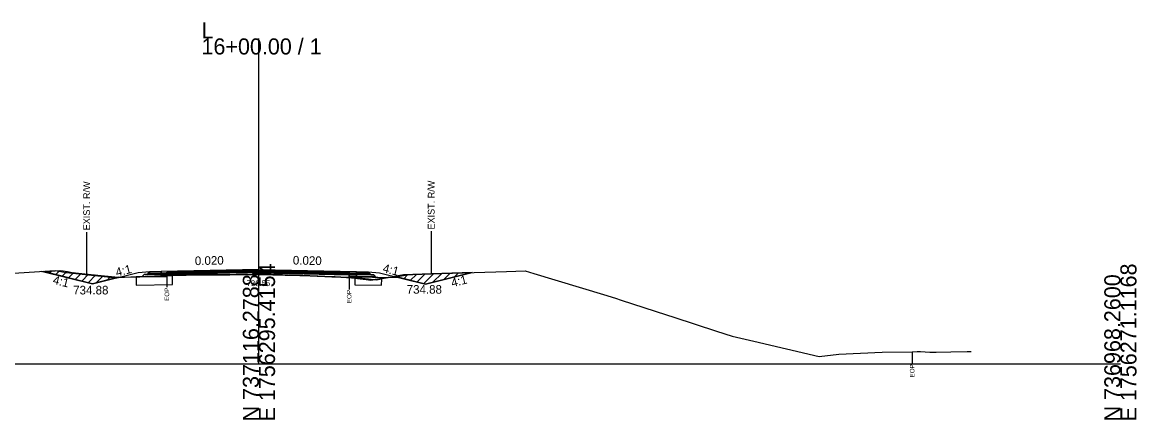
# Model space of a CAD drawing. Extents: x -26 to 4303, y -10 to 9577.
# Drawn here: x 108.8 to 302.8, y 5990.3 to 6059.4 of the extents above; entities that cross this region are included whole.
import ezdxf

# ---------------------------------------------------------------- set-up
doc = ezdxf.new("R2010")
doc.units = 0
for name, color, linetype in [('Exist CMT Pavement', 7, 'Continuous'), ('Old_Level_2', 7, 'Continuous'), ('Pattern 1', 7, 'Continuous'), ('Prop CMT Conc Surface', 7, 'Continuous'), ('Prop CMT Concrete Structures', 7, 'Continuous'), ('Prop CMT Pvmt Course 1', 7, 'Continuous'), ('Prop CMT Pvmt Course 1 CG', 7, 'Continuous'), ('Prop CMT Pvmt Course 1 Wedge', 7, 'Continuous'), ('Prop CMT Pvmt Course 2', 7, 'Continuous'), ('Prop CMT Pvmt Course 2 Wedge', 7, 'Continuous'), ('Prop CMT Pvmt Course 3', 7, 'Continuous'), ('Prop CMT Pvmt Surface', 7, 'Continuous'), ('Prop CMT Pvmt Surface Shoulder', 7, 'Continuous'), ('Prop CMT Pvmt Wedge Surface 1', 7, 'Continuous'), ('Prop CMT Pvmt Wedge Surface 2', 7, 'Continuous'), ('Prop CMT Pvmt Wedge Surface 3', 7, 'Continuous'), ('Prop CMT Shld Paved Course 1', 7, 'Continuous'), ('Prop CMT Shld Paved Course 2', 7, 'Continuous'), ('Prop CMT Shld Paved Course 3', 7, 'Continuous'), ('Prop CMT Slope Grass', 7, 'Continuous'), ('Prop CMT Subgrade Earthwork', 7, 'Continuous'), ('Prop Road Sect_ Recs - UC Shallow (Outline)', 7, 'Continuous'), ('Prop Shade Light', 7, 'Continuous'), ('Prop XS DDE Elevations', 7, 'Continuous'), ('Prop XS Ditch Standard Text', 7, 'Continuous'), ('Prop XS Hydro Elevations', 7, 'Continuous'), ('Prop XS SE Text', 7, 'Continuous'), ('Prop XS Side Slope Text', 7, 'Continuous'), ('Prop XS Wedging', 7, 'Continuous')]:
    doc.layers.add(name, color=color, linetype=linetype)

msp = doc.modelspace()

# ---------------------------------------------------------------- linework, layer by layer
at = {"layer": 'Exist CMT Pavement'}
for points in [[(150, 6016.42), (133, 6016.08)], [(150, 6016.42), (167, 6016.08)]]:
    msp.add_lwpolyline(points, dxfattribs=at)
at = {"layer": 'Old_Level_2'}
for p, q in [((150, 6000), (150, 6056.65)), ((150, 6000), (150, 6056.65)), ((0, 6000), (150, 6000)), ((0, 6000), (150, 6000)), ((150, 6000), (300, 6000)), ((150, 6000), (300, 6000))]:
    msp.add_line(p, q, dxfattribs=at)
at = {"layer": 'Pattern 1'}
for p, q in [((113.48, 6015.84), (113.81, 6016.16)), ((114.61, 6015.55), (115.32, 6016.26)), ((115.74, 6015.27), (116.56, 6016.09)), ((116.87, 6014.99), (117.79, 6015.9)), ((118.01, 6014.7), (119.06, 6015.76)), ((119.14, 6014.42), (120.34, 6015.63)), ((120.27, 6014.14), (121.62, 6015.49)), ((121.67, 6014.12), (122.9, 6015.35)), ((175.29, 6014.88), (175.84, 6015.43)), ((176.42, 6014.6), (177.36, 6015.53)), ((177.56, 6014.32), (178.83, 6015.59)), ((178.69, 6014.03), (180.31, 6015.65)), ((180.36, 6014.3), (181.77, 6015.7)), ((182.25, 6014.77), (183.23, 6015.75)), ((184.13, 6015.24), (184.7, 6015.8)), ((186.02, 6015.71), (186.16, 6015.85)), ((123.55, 6014.59), (124.17, 6015.22)), ((125.44, 6015.06), (125.45, 6015.08)), ((125.84, 6015.09), (125.85, 6015.1)), ((125.85, 6015.1), (125.85, 6015.1))]:
    msp.add_line(p, q, dxfattribs=at)
for points in [[(125.48, 6015.08), (121, 6013.96), (112.51, 6016.08), (115.5, 6016.27), (116.65, 6016.07), (117.47, 6015.93), (121.38, 6015.51)], [(179, 6013.96), (186.64, 6015.86), (185.58, 6015.83), (180.42, 6015.66), (176.36, 6015.49), (175.82, 6015.43), (174.17, 6015.16)]]:
    msp.add_lwpolyline(points, close=True, dxfattribs=at)
msp.add_lwpolyline([(134.96, 6015.42), (134.96, 6015.32), (130.32, 6015.22), (132.36, 6015.31), (133.86, 6015.38), (134.96, 6015.42)], dxfattribs=at)
at = {"layer": 'Prop CMT Conc Surface'}
for points in [[(133.97, 6015.85), (133, 6015.83)], [(133, 6015.83), (133, 6015.62)], [(133, 6015.62), (133.97, 6015.64)], [(133.97, 6015.64), (133.97, 6015.85)], [(165.71, 6015.65), (165.71, 6015.86)], [(165.71, 6015.86), (167, 6015.83)], [(167, 6015.62), (165.71, 6015.65)], [(167, 6015.83), (167, 6015.62)]]:
    msp.add_lwpolyline(points, dxfattribs=at)
at = {"layer": 'Prop CMT Concrete Structures'}
for points in [[(133, 6015.83), (133, 6016.08)], [(133.97, 6015.85), (133, 6015.83)], [(150, 6016.3), (133.97, 6015.98)], [(133.97, 6015.98), (133.97, 6015.85)], [(150, 6016.3), (165.71, 6015.98)], [(165.71, 6015.98), (165.71, 6015.86)], [(165.71, 6015.86), (167, 6015.83)], [(167, 6015.83), (167, 6016.08)]]:
    msp.add_lwpolyline(points, dxfattribs=at)
at = {"layer": 'Prop CMT Pvmt Course 1'}
for points in [[(133.97, 6015.64), (133, 6015.62)], [(133, 6015.62), (133, 6015.29)], [(133.97, 6015.31), (133.97, 6015.64)], [(165.71, 6015.65), (167, 6015.62)], [(165.71, 6015.19), (165.71, 6015.65)], [(167, 6015.62), (167, 6015.29)], [(133, 6015.29), (133.97, 6015.31)], [(167, 6015.29), (165.71, 6015.32)]]:
    msp.add_lwpolyline(points, dxfattribs=at)
at = {"layer": 'Prop CMT Pvmt Course 1 Wedge'}
for points in [[(133.97, 6015.64), (134.04, 6015.65), (134.07, 6015.65), (134.14, 6015.65), (134.98, 6015.66), (135.35, 6015.67), (137.23, 6015.71), (137.36, 6015.71), (138.42, 6015.73), (139.9, 6015.76), (140.59, 6015.78), (142.43, 6015.81), (142.77, 6015.82), (144.85, 6015.86), (144.96, 6015.86), (146.02, 6015.89), (146.32, 6015.89), (146.51, 6015.89), (146.58, 6015.9), (147.02, 6015.9), (147.14, 6015.91), (147.5, 6015.91), (148.02, 6015.92), (150, 6015.96)], [(133.97, 6015.42), (133.97, 6015.64)], [(150, 6015.55), (148.02, 6015.58), (147.5, 6015.58), (147.14, 6015.57), (147.02, 6015.58), (146.58, 6015.57), (146.51, 6015.57), (146.32, 6015.57), (146.02, 6015.56), (144.96, 6015.54), (144.85, 6015.54), (142.77, 6015.54), (142.43, 6015.54), (140.59, 6015.52), (139.9, 6015.51), (138.42, 6015.49), (137.36, 6015.47), (137.23, 6015.47), (135.35, 6015.47), (134.98, 6015.45), (134.14, 6015.43), (134.07, 6015.43), (134.04, 6015.43), (133.97, 6015.42)], [(150, 6015.96), (150, 6015.55)], [(150, 6015.96), (150.03, 6015.96), (151.47, 6015.94), (151.98, 6015.92), (152.41, 6015.92), (152.91, 6015.91), (153.24, 6015.9), (154.08, 6015.88), (154.56, 6015.87), (155.1, 6015.86), (157.11, 6015.82), (157.63, 6015.81), (160.14, 6015.76), (160.16, 6015.76), (160.28, 6015.76), (162.7, 6015.71), (163.25, 6015.7), (165.27, 6015.66), (165.28, 6015.66), (165.28, 6015.66), (165.28, 6015.66), (165.45, 6015.66), (165.49, 6015.65), (165.5, 6015.65), (165.59, 6015.65), (165.71, 6015.65)], [(165.71, 6015.03), (165.59, 6015.05), (165.5, 6015.05), (165.49, 6015.05), (165.45, 6015.06), (165.28, 6015.06), (165.28, 6015.06), (165.28, 6015.06), (165.27, 6015.06), (163.25, 6015.16), (162.7, 6015.18), (160.28, 6015.27), (160.16, 6015.27), (160.14, 6015.27), (157.63, 6015.38), (157.11, 6015.4), (155.1, 6015.46), (154.56, 6015.47), (154.08, 6015.49), (153.24, 6015.51), (152.91, 6015.52), (152.41, 6015.54), (151.98, 6015.55), (151.47, 6015.55), (150.03, 6015.55), (150, 6015.55)], [(165.71, 6015.65), (165.71, 6015.03)]]:
    msp.add_lwpolyline(points, dxfattribs=at)
at = {"layer": 'Prop CMT Pvmt Course 2'}
for points in [[(133, 6016.08), (131, 6016.04), (130.74, 6015.79)], [(130.74, 6015.79), (133, 6015.83)], [(133, 6015.83), (133, 6016.08)], [(167, 6016.08), (169, 6016.04), (169.26, 6015.79)], [(167, 6015.83), (167, 6016.08)], [(169.26, 6015.79), (167, 6015.83)]]:
    msp.add_lwpolyline(points, dxfattribs=at)
at = {"layer": 'Prop CMT Pvmt Course 2 Wedge'}
for points in [[(131, 6016.04), (129, 6015.88), (121, 6013.88), (112.08, 6016.11)], [(169, 6016.04), (171, 6015.88), (179, 6013.88), (187.13, 6015.91)]]:
    msp.add_lwpolyline(points, dxfattribs=at)
at = {"layer": 'Prop CMT Pvmt Course 3'}
for points in [[(133, 6015.83), (130.74, 6015.79), (130.53, 6015.58)], [(130.53, 6015.58), (133, 6015.62)], [(133, 6015.62), (133, 6015.83)], [(167, 6015.83), (169.26, 6015.79), (169.47, 6015.58)], [(167, 6015.62), (167, 6015.83)], [(169.47, 6015.58), (167, 6015.62)]]:
    msp.add_lwpolyline(points, dxfattribs=at)
at = {"layer": 'Prop CMT Pvmt Surface'}
for points in [[(150, 6016.17), (133, 6015.83)], [(133, 6015.83), (133, 6016.08)], [(150, 6016.17), (167, 6015.83)], [(167, 6015.83), (167, 6016.08)]]:
    msp.add_lwpolyline(points, dxfattribs=at)
at = {"layer": 'Prop CMT Pvmt Surface Shoulder'}
for points in [[(133.97, 6015.42), (134.04, 6015.43), (134.07, 6015.43), (134.14, 6015.43), (134.98, 6015.45), (135.35, 6015.47), (137.23, 6015.47), (137.36, 6015.47), (138.42, 6015.49), (139.9, 6015.51), (140.59, 6015.52), (142.43, 6015.54), (142.77, 6015.54), (144.85, 6015.54), (144.96, 6015.54), (146.02, 6015.56), (146.32, 6015.57), (146.51, 6015.57), (146.58, 6015.57), (147.02, 6015.58), (147.14, 6015.57), (147.5, 6015.58), (148.02, 6015.58), (150, 6015.55)], [(150, 6015.55), (150.03, 6015.55), (151.47, 6015.55), (151.98, 6015.55), (152.41, 6015.54), (152.91, 6015.52), (153.24, 6015.51), (154.08, 6015.49), (154.56, 6015.47), (155.1, 6015.46), (157.11, 6015.4), (157.63, 6015.38), (160.14, 6015.27), (160.16, 6015.27), (160.28, 6015.27), (162.7, 6015.18), (163.25, 6015.16), (165.27, 6015.06), (165.28, 6015.06), (165.28, 6015.06), (165.28, 6015.06), (165.45, 6015.06), (165.49, 6015.05), (165.5, 6015.05), (165.59, 6015.05), (165.7, 6015.03)]]:
    msp.add_lwpolyline(points, dxfattribs=at)
at = {"layer": 'Prop CMT Pvmt Wedge Surface 1'}
for p, q in [((133.02, 6015.17), (125.53, 6015.02)), ((133.97, 6015.19), (133.02, 6015.17)), ((165.7, 6015.19), (166.98, 6015.17)), ((166.98, 6015.17), (174.47, 6015.02))]:
    msp.add_line(p, q, dxfattribs=at)
for points in [[(133.97, 6015.19), (133.97, 6015.42)], [(165.7, 6015.19), (165.7, 6015.03)]]:
    msp.add_lwpolyline(points, dxfattribs=at)
at = {"layer": 'Prop CMT Pvmt Wedge Surface 2'}
for points in [[(133.97, 6015.98), (134.04, 6015.98), (134.07, 6015.98), (134.14, 6015.98), (134.98, 6016), (135.35, 6016), (137.23, 6016.04), (137.36, 6016.05), (138.42, 6016.07), (139.9, 6016.1), (140.59, 6016.11), (142.43, 6016.15), (142.77, 6016.15), (144.85, 6016.19), (144.96, 6016.2), (146.02, 6016.22), (146.32, 6016.22), (146.51, 6016.23), (146.58, 6016.23), (147.02, 6016.24), (147.14, 6016.24), (147.5, 6016.25), (148.02, 6016.26), (150, 6016.3)], [(150, 6016.17), (148.02, 6016.13), (147.5, 6016.12), (147.14, 6016.12), (147.02, 6016.11), (146.58, 6016.1), (146.51, 6016.1), (146.32, 6016.1), (146.02, 6016.09), (144.96, 6016.07), (144.85, 6016.07), (142.77, 6016.03), (142.43, 6016.02), (140.59, 6015.98), (139.9, 6015.97), (138.42, 6015.94), (137.36, 6015.92), (137.23, 6015.92), (135.35, 6015.88), (134.98, 6015.87), (134.14, 6015.86), (134.07, 6015.85), (134.04, 6015.85), (133.97, 6015.85)], [(133.97, 6015.85), (133.97, 6015.98)], [(150, 6016.3), (150, 6016.17)], [(150, 6016.3), (150.03, 6016.3), (151.47, 6016.27), (151.98, 6016.26), (152.41, 6016.25), (152.91, 6016.24), (153.24, 6016.23), (154.08, 6016.22), (154.56, 6016.21), (155.1, 6016.2), (157.11, 6016.16), (157.63, 6016.15), (160.14, 6016.1), (160.16, 6016.09), (160.28, 6016.09), (162.7, 6016.04), (163.25, 6016.03), (165.27, 6015.99), (165.28, 6015.99), (165.28, 6015.99), (165.28, 6015.99), (165.45, 6015.99), (165.49, 6015.99), (165.5, 6015.99), (165.59, 6015.99), (165.71, 6015.98)], [(165.71, 6015.86), (165.59, 6015.86), (165.5, 6015.86), (165.49, 6015.86), (165.45, 6015.86), (165.28, 6015.87), (165.28, 6015.87), (165.28, 6015.87), (165.27, 6015.87), (163.25, 6015.91), (162.7, 6015.92), (160.28, 6015.97), (160.16, 6015.97), (160.14, 6015.97), (157.63, 6016.02), (157.11, 6016.03), (155.1, 6016.07), (154.56, 6016.08), (154.08, 6016.09), (153.24, 6016.11), (152.91, 6016.11), (152.41, 6016.12), (151.98, 6016.13), (151.47, 6016.14), (150.03, 6016.17), (150, 6016.17)], [(165.71, 6015.98), (165.71, 6015.86)]]:
    msp.add_lwpolyline(points, dxfattribs=at)
at = {"layer": 'Prop CMT Pvmt Wedge Surface 3'}
for points in [[(133.97, 6015.85), (134.04, 6015.85), (134.07, 6015.85), (134.14, 6015.86), (134.98, 6015.87), (135.35, 6015.88), (137.23, 6015.92), (137.36, 6015.92), (138.42, 6015.94), (139.9, 6015.97), (140.59, 6015.98), (142.43, 6016.02), (142.77, 6016.03), (144.85, 6016.07), (144.96, 6016.07), (146.02, 6016.09), (146.32, 6016.1), (146.51, 6016.1), (146.58, 6016.1), (147.02, 6016.11), (147.14, 6016.12), (147.5, 6016.12), (148.02, 6016.13), (150, 6016.17)], [(150, 6015.96), (148.02, 6015.92), (147.5, 6015.91), (147.14, 6015.91), (147.02, 6015.9), (146.58, 6015.9), (146.51, 6015.89), (146.32, 6015.89), (146.02, 6015.89), (144.96, 6015.86), (144.85, 6015.86), (142.77, 6015.82), (142.43, 6015.81), (140.59, 6015.78), (139.9, 6015.76), (138.42, 6015.73), (137.36, 6015.71), (137.23, 6015.71), (135.35, 6015.67), (134.98, 6015.66), (134.14, 6015.65), (134.07, 6015.65), (134.04, 6015.65), (133.97, 6015.64)], [(133.97, 6015.64), (133.97, 6015.85)], [(150, 6016.17), (150, 6015.96)], [(150, 6016.17), (150.03, 6016.17), (151.47, 6016.14), (151.98, 6016.13), (152.41, 6016.12), (152.91, 6016.11), (153.24, 6016.11), (154.08, 6016.09), (154.56, 6016.08), (155.1, 6016.07), (157.11, 6016.03), (157.63, 6016.02), (160.14, 6015.97), (160.16, 6015.97), (160.28, 6015.97), (162.7, 6015.92), (163.25, 6015.91), (165.27, 6015.87), (165.28, 6015.87), (165.28, 6015.87), (165.28, 6015.87), (165.45, 6015.86), (165.49, 6015.86), (165.5, 6015.86), (165.59, 6015.86), (165.71, 6015.86)], [(165.71, 6015.65), (165.59, 6015.65), (165.5, 6015.65), (165.49, 6015.65), (165.45, 6015.66), (165.28, 6015.66), (165.28, 6015.66), (165.28, 6015.66), (165.27, 6015.66), (163.25, 6015.7), (162.7, 6015.71), (160.28, 6015.76), (160.16, 6015.76), (160.14, 6015.76), (157.63, 6015.81), (157.11, 6015.82), (155.1, 6015.86), (154.56, 6015.87), (154.08, 6015.88), (153.24, 6015.9), (152.91, 6015.91), (152.41, 6015.92), (151.98, 6015.92), (151.47, 6015.94), (150.03, 6015.96), (150, 6015.96)], [(165.71, 6015.86), (165.71, 6015.65)]]:
    msp.add_lwpolyline(points, dxfattribs=at)
at = {"layer": 'Prop CMT Shld Paved Course 1'}
for points in [[(133, 6015.62), (133, 6016.08)], [(150, 6015.96), (133, 6015.62)], [(150, 6015.96), (167, 6015.62)], [(167, 6015.62), (167, 6016.08)]]:
    msp.add_lwpolyline(points, dxfattribs=at)
at = {"layer": 'Prop CMT Shld Paved Course 2'}
for points in [[(133, 6016.08), (131, 6016.04)], [(167, 6016.08), (169, 6016.04)]]:
    msp.add_lwpolyline(points, dxfattribs=at)
at = {"layer": 'Prop CMT Shld Paved Course 3'}
for points in [[(150, 6016.42), (133, 6016.08)], [(133, 6016.08), (133, 6015.83)], [(133, 6015.83), (133.97, 6015.85)], [(133.97, 6015.98), (150, 6016.3)], [(133.97, 6015.85), (133.97, 6015.98)], [(150, 6016.42), (167, 6016.08)], [(165.71, 6015.98), (150, 6016.3)], [(165.71, 6015.86), (165.71, 6015.98)], [(167, 6015.83), (165.71, 6015.86)], [(167, 6016.08), (167, 6015.83)]]:
    msp.add_lwpolyline(points, dxfattribs=at)
at = {"layer": 'Prop CMT Slope Grass'}
msp.add_lwpolyline([(106.37, 6015.74), (114.51, 6016.27), (116.45, 6015.94), (124.76, 6015.05), (125.14, 6015.07), (129.54, 6015.23), (134.04, 6015.43), (134.98, 6015.45), (135.35, 6015.47), (137.36, 6015.47), (138.42, 6015.49), (139.9, 6015.51), (140.59, 6015.52), (142.43, 6015.54), (144.96, 6015.54), (146.02, 6015.56), (146.51, 6015.57), (147.14, 6015.57), (147.5, 6015.58), (148.02, 6015.58), (150.03, 6015.55), (151.47, 6015.55), (152.56, 6015.53), (152.91, 6015.52), (154.06, 6015.49), (154.56, 6015.47), (155.1, 6015.46), (157.11, 6015.4), (157.63, 6015.38), (160.28, 6015.27), (162.7, 6015.18), (163.25, 6015.16), (165.49, 6015.05), (165.59, 6015.05), (168.69, 6014.68), (169.44, 6014.58), (171.82, 6014.95), (175.19, 6015.49), (180.05, 6015.68), (181.84, 6015.74), (193.13, 6016.11), (196.35, 6016.23), (197.88, 6015.76), (210.01, 6012.07), (212.11, 6011.43), (213.09, 6011.11), (220.95, 6008.56), (222.24, 6008.14), (229.66, 6005.69), (232.38, 6004.85), (236.15, 6003.99), (247.52, 6001.31), (250.99, 6001.73), (258.5, 6002.07), (263.74, 6002.11), (264.63, 6002.18), (265.2, 6002.18), (266.79, 6002.06), (267.93, 6002.04), (270.5, 6002.11), (273.32, 6002.17), (273.99, 6002.18)], dxfattribs=at)
at = {"layer": 'Prop CMT Subgrade Earthwork'}
for points in [[(133, 6015.62), (130.53, 6015.58), (130.03, 6015.57), (129.69, 6015.23)], [(133, 6015.29), (133, 6015.62)], [(167, 6015.62), (169.47, 6015.58), (169.97, 6015.57), (170.31, 6015.23)], [(167, 6015.29), (167, 6015.62)], [(129.69, 6015.23), (133, 6015.29)], [(170.31, 6015.23), (167, 6015.29)]]:
    msp.add_lwpolyline(points, dxfattribs=at)
at = {"layer": 'Prop Road Sect_ Recs - UC Shallow (Outline)'}
for points in [[(128.64, 6013.69), (134.96, 6013.82), (134.96, 6015.32), (130.2, 6015.22), (128.61, 6015.16)], [(166.7, 6013.79), (171.36, 6013.69), (171.38, 6014.73), (170.44, 6014.58), (169.06, 6014.76), (167.4, 6014.95), (166.7, 6015.03)]]:
    msp.add_lwpolyline(points, close=True, dxfattribs=at)
at = {"layer": 'Prop Shade Light'}
for points in [[(128.64, 6013.69), (134.96, 6013.82), (134.96, 6015.32), (130.2, 6015.22), (128.61, 6015.16), (128.64, 6013.69)], [(166.7, 6013.79), (171.36, 6013.69), (171.38, 6014.73), (170.44, 6014.58), (169.06, 6014.76), (167.4, 6014.95), (166.7, 6015.03), (166.7, 6013.79)]]:
    msp.add_lwpolyline(points, dxfattribs=at)
at = {"layer": 'Prop XS DDE Elevations'}
for points in [[(116.45, 6015.94), (124.76, 6015.05), (125.14, 6015.07), (125.85, 6015.1), (125.53, 6015.02), (121, 6013.88), (112.08, 6016.11), (114.51, 6016.27)], [(129.54, 6015.23), (133.97, 6015.42), (133.97, 6015.19), (133.02, 6015.17), (125.53, 6015.02), (125.85, 6015.1)], [(134.04, 6015.43), (134.98, 6015.45), (134.14, 6015.43), (134.07, 6015.43)], [(135.35, 6015.47), (137.23, 6015.47), (137.36, 6015.47)], [(146.32, 6015.57), (146.51, 6015.57), (146.02, 6015.56)], [(146.51, 6015.57), (146.58, 6015.57), (146.72, 6015.57)], [(147.02, 6015.58), (147.14, 6015.57), (146.72, 6015.57)], [(152.41, 6015.54), (152.56, 6015.53), (151.47, 6015.55), (151.98, 6015.55)], [(154.08, 6015.49), (154.56, 6015.47), (154.06, 6015.49), (152.91, 6015.52), (153.24, 6015.51)], [(157.63, 6015.38), (160.28, 6015.27), (160.16, 6015.27), (160.14, 6015.27)], [(179, 6013.88), (187.13, 6015.91), (181.84, 6015.74), (180.05, 6015.68), (175.19, 6015.49), (173.6, 6015.23), (174.47, 6015.02)], [(163.25, 6015.16), (165.28, 6015.06), (165.27, 6015.06)], [(165.45, 6015.06), (165.49, 6015.05), (165.28, 6015.06)], [(165.7, 6015.19), (166.98, 6015.17), (172.49, 6015.06), (171.82, 6014.95), (169.44, 6014.58), (168.69, 6014.68), (165.7, 6015.03)], [(172.49, 6015.06), (173.6, 6015.23), (174.47, 6015.02)]]:
    msp.add_lwpolyline(points, close=True, dxfattribs=at)
at = {"layer": 'Prop XS Ditch Standard Text'}
for p, q in [((120, 6022.96), (120, 6015.56)), ((180, 6023.08), (180, 6015.68)), ((133.97, 6015.42), (133.97, 6013.37)), ((165.71, 6015.03), (165.71, 6012.98)), ((263.74, 6002.11), (263.74, 6000.06))]:
    msp.add_line(p, q, dxfattribs=at)
at = {"layer": 'Prop XS Wedging'}
for p, q in [((150, 6016.3), (133.97, 6015.98)), ((133.97, 6015.85), (150, 6016.17)), ((133.97, 6015.85), (150, 6016.17)), ((133.97, 6015.98), (133.97, 6015.85)), ((133.97, 6015.85), (133.97, 6015.64)), ((133.97, 6015.64), (133.97, 6015.42)), ((149, 6015.82), (148.76, 6015.56)), ((149, 6015.82), (148.76, 6015.56)), ((148.76, 6015.56), (149, 6015.82)), ((149, 6015.82), (150.01, 6015.84)), ((165.71, 6015.53), (149.99, 6015.84)), ((165.71, 6015.98), (150, 6016.3)), ((165.7, 6015.86), (150, 6016.17)), ((150, 6016.17), (165.71, 6015.86)), ((150, 6016.17), (150, 6016.17)), ((165.71, 6015.86), (165.71, 6015.98)), ((165.71, 6015.65), (165.71, 6015.86)), ((165.71, 6015.53), (165.71, 6015.65)), ((165.7, 6015.03), (165.71, 6015.19)), ((165.7, 6015.03), (165.7, 6015.03))]:
    msp.add_line(p, q, dxfattribs=at)
for points in [[(150, 6016.17), (150, 6016.17), (133.97, 6015.85)], [(133.97, 6015.42), (134.04, 6015.43), (134.98, 6015.45), (135.35, 6015.47), (137.36, 6015.47), (138.42, 6015.49), (139.9, 6015.51), (140.59, 6015.52), (142.43, 6015.54), (144.96, 6015.54), (146.02, 6015.56), (146.51, 6015.57), (147.14, 6015.57), (147.5, 6015.58), (148.02, 6015.58), (148.76, 6015.56)], [(133.97, 6015.42), (133.97, 6015.42), (133.97, 6015.42)], [(148.76, 6015.56), (150.03, 6015.55), (151.47, 6015.55), (152.56, 6015.53), (152.91, 6015.52), (154.06, 6015.49), (154.56, 6015.47), (155.1, 6015.46), (157.11, 6015.4), (157.63, 6015.38), (160.28, 6015.27), (162.7, 6015.18), (163.25, 6015.16), (165.49, 6015.05), (165.59, 6015.05), (165.7, 6015.03)], [(150, 6015.84), (149.99, 6015.84), (149, 6015.82)], [(149, 6015.82), (149.99, 6015.84), (150, 6015.84)], [(165.71, 6015.86), (150, 6016.17), (150, 6016.17)], [(165.71, 6015.53), (150.01, 6015.84), (150, 6015.84)], [(150, 6015.84), (150.01, 6015.84), (165.71, 6015.53)], [(165.71, 6015.19), (165.71, 6015.32), (165.71, 6015.53)]]:
    msp.add_lwpolyline(points, dxfattribs=at)

# ---------------------------------------------------------------- texts
at = {"layer": 'Old_Level_2'}
for s, p in [('L', (140, 6056.65)), ('L', (140, 6056.65)), ('16+00.00 / 1', (140, 6053.85)), ('16+00.00 / 1', (140, 6053.85))]:
    msp.add_text(s, height=2.8, dxfattribs=at).set_placement(p)
for s, p in [('E 1756295.4154', (152.8, 5990)), ('E 1756295.4154', (152.8, 5990)), ('E 1756271.1168', (302.8, 5990)), ('E 1756271.1168', (302.8, 5990)), ('N 737116.2788', (150, 5990)), ('N 737116.2788', (150, 5990)), ('N 736968.2600', (300, 5990)), ('N 736968.2600', (300, 5990))]:
    msp.add_text(s, height=2.8, rotation=90, dxfattribs=at).set_placement(p)
at = {"layer": 'Prop CMT Pvmt Course 1 CG'}
msp.add_text('736.55', height=1, dxfattribs=at).set_placement((147.87, 6013.55))
at = {"layer": 'Prop XS Ditch Standard Text'}
for s, height, p in [('EXIST. R/W', 1.181, (120.59, 6023.26)), ('EXIST. R/W', 1.181, (180.59, 6023.39)), ('EOP', 0.787, (134.37, 6010.98)), ('EOP', 0.787, (166.1, 6010.59)), ('EOP', 0.787, (264.13, 5997.66))]:
    msp.add_text(s, height=height, rotation=90, dxfattribs=at).set_placement(p)
at = {"layer": 'Prop XS Hydro Elevations'}
for p in [(117.66, 6012.1), (175.73, 6012.23)]:
    msp.add_text('734.88', height=1.5, dxfattribs=at).set_placement(p)
at = {"layer": 'Prop XS SE Text'}
for rotation, p in [(1.1458, (138.86, 6017.2)), (358.8542, (155.9, 6017.31))]:
    msp.add_text('0.020', height=1.5, rotation=rotation, dxfattribs=at).set_placement(p)
at = {"layer": 'Prop XS Side Slope Text'}
for rotation, p in [(345.9638, (171.45, 6016)), (14.0362, (125.24, 6015.19)), (14.0362, (183.67, 6013.36)), (345.9638, (114.02, 6013.98))]:
    msp.add_text('4:1', height=1.5, rotation=rotation, dxfattribs=at).set_placement(p)

doc.saveas('drawing.dxf')
